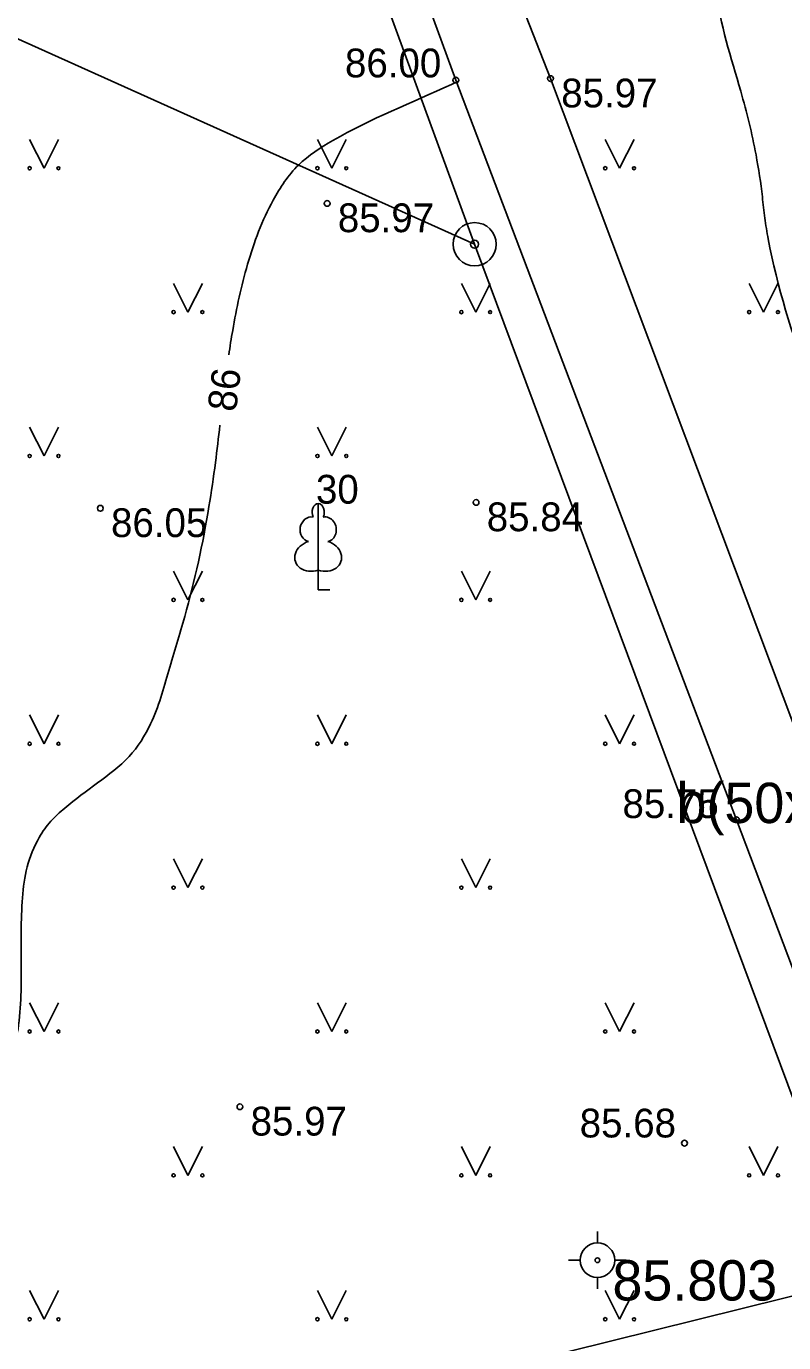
# Model space of a CAD drawing. Extents: x 576692 to 577659, y 273254 to 273799.
# Drawn here: x 576757.19 to 576770.35, y 273657.09 to 273679.97 of the extents above; entities that cross this region are included whole.
import ezdxf

# ---------------------------------------------------------------- set-up
doc = ezdxf.new("R2010")
doc.units = 0
for name, color, linetype in [('APGR_SARK_####_####_#', 7, 'Continuous'), ('BUVE_EKAS_RAKS_TKST_#', 7, 'Continuous'), ('CELI_CAPM_####_####_#', 7, 'Continuous'), ('CELI_CMAL_####_####_#', 7, 'Continuous'), ('CELI_TAKA_####_####_#', 7, 'Continuous'), ('CKOM_DEGV_ELEM_TKST_#', 7, 'Continuous'), ('CKOM_ELEM_####_####_#', 7, 'Continuous'), ('GEOD_ELEM_####_TKST_#', 7, 'Continuous'), ('GEOD_SITP_####_TKST_#', 7, 'Continuous'), ('HIDT_REZV_####_TKST_#', 7, 'Continuous'), ('LKAN_ELEM_PAST_TKST_#', 7, 'Continuous'), ('RELJ_ELEM_####_####_#', 7, 'Continuous'), ('RELJ_HORZ_PAMT_####_#', 7, 'Continuous'), ('SILT_VADP_UDEN_####_#', 7, 'Continuous')]:
    doc.layers.add(name, color=color, linetype=linetype)

msp = doc.modelspace()

# ---------------------------------------------------------------- linework, layer by layer
at = {"layer": 'BUVE_EKAS_RAKS_TKST_#'}
for radius in [0.375, 0.0702]:
    msp.add_circle((576764.98, 273676.18), radius, dxfattribs=at)
at = {"layer": 'CELI_CAPM_####_####_#'}
for points in [[(576773.869, 273658.741), (576773.854, 273658.784), (576773.503, 273659.803), (576770.984, 273666.605), (576766.299, 273679.057), (576764.543, 273683.538), (576764.259, 273684.554), (576764.25, 273685.513), (576764.288, 273686.523), (576764.428, 273692.633), (576764.527, 273693.163), (576767.396, 273701.827), (576768.01, 273703.188), (576772.621, 273713.302), (576777.579, 273724.305)], [(576775.322, 273724.131), (576774.601, 273722.477), (576775.024, 273722.324), (576771.324, 273714.127), (576766.646, 273703.83), (576766.03, 273702.46), (576765.472, 273700.84), (576763.518, 273694.624), (576763.117, 273693.591), (576762.914, 273692.62), (576762.805, 273686.629), (576762.771, 273685.624), (576762.737, 273684.906), (576763.015, 273683.516), (576764.654, 273679.032), (576769.528, 273666.179), (576772.041, 273659.532), (576772.286, 273658.824), (576772.437, 273658.386)]]:
    msp.add_lwpolyline(points, dxfattribs=at)
at = {"layer": 'CELI_TAKA_####_####_#'}
msp.add_lwpolyline([(576848.447, 273595.284), (576850.413, 273611.975), (576839.74, 273611.3), (576799.298, 273680.086), (576786.491, 273690.257), (576780.2, 273683.233), (576786.155, 273661.79), (576765.1, 273656.565), (576764.662, 273653.384), (576732.149, 273649.138), (576726.076, 273650.997), (576719.157, 273649.712), (576724.595, 273660.398), (576733.342, 273685.822), (576746.079, 273731.492)], dxfattribs=at)
at = {"layer": 'CKOM_ELEM_####_####_#'}
for p, q in [((576767.114, 273658.826), (576767.114, 273659.026)), ((576766.614, 273658.526), (576766.814, 273658.526)), ((576767.414, 273658.526), (576767.614, 273658.526)), ((576767.114, 273658.026), (576767.114, 273658.226))]:
    msp.add_line(p, q, dxfattribs=at)
for radius in [0.3, 0.04]:
    msp.add_circle((576767.114, 273658.526), radius, dxfattribs=at)
at = {"layer": 'GEOD_ELEM_####_TKST_#'}
for points in [[(576764.625, 273678.98), (576764.576, 273678.957), (576762.517, 273677.983), (576761.92, 273677.555), (576761.679, 273677.268), (576761.479, 273676.944), (576761.036, 273675.831), (576760.777, 273674.683), (576760.709, 273674.255)], [(576760.556, 273673.037), (576760.477, 273672.385), (576760.365, 273671.62), (576759.945, 273669.712), (576759.669, 273668.774), (576759.351, 273667.846), (576758.977, 273667.278), (576758.429, 273666.82), (576757.86, 273666.381), (576757.617, 273666.152), (576757.511, 273666.02), (576757.418, 273665.873), (576757.206, 273665.36), (576757.125, 273664.825), (576757.103, 273663.643), (576757.036, 273662.469), (576756.887, 273661.93), (576756.608, 273661.447), (576755.986, 273660.73), (576755.306, 273660.08), (576754.566, 273659.505), (576753.765, 273659.015), (576752.999, 273658.642), (576752.222, 273658.3), (576751.454, 273657.95), (576750.71, 273657.551), (576747.619, 273655.722), (576746.907, 273655.289), (576746.201, 273654.848), (576745.493, 273654.408), (576745.12, 273654.182)]]:
    msp.add_spline(points, degree=3, dxfattribs=at)
at = {"layer": 'GEOD_SITP_####_TKST_#'}
msp.add_spline([(576771.012, 273694.903), (576770.897, 273694.749), (576770.848, 273694.681), (576770.769, 273694.511), (576770.586, 273693.743), (576769.497, 273689.762), (576769.267, 273688.405), (576769.27, 273687.222), (576769.378, 273686.039), (576769.501, 273684.856), (576769.548, 273683.673), (576769.52, 273683.23), (576769.451, 273682.81), (576769.357, 273682.394), (576769.262, 273681.979), (576769.188, 273681.562), (576769.176, 273680.6), (576769.604, 273678.839), (576769.869, 273677.731), (576769.979, 273677.003), (576770.021, 273676.635), (576770.081, 273676.271), (576770.793, 273673.833), (576771.261, 273672.65), (576771.782, 273671.484), (576771.987, 273671.135), (576772.039, 273670.993), (576772.601, 273667.751), (576772.598, 273666.644), (576772.546, 273666.09), (576772.472, 273665.54), (576772.28, 273664.711), (576771.998, 273663.9)], degree=3, dxfattribs=at)
at = {"layer": 'LKAN_ELEM_PAST_TKST_#'}
for p, q in [((576757.25, 273678), (576757.5, 273677.5)), ((576757.5, 273677.5), (576757.75, 273678)), ((576762.25, 273678), (576762.5, 273677.5)), ((576762.5, 273677.5), (576762.75, 273678)), ((576767.25, 273678), (576767.5, 273677.5)), ((576767.5, 273677.5), (576767.75, 273678)), ((576759.75, 273675.5), (576760, 273675)), ((576760, 273675), (576760.25, 273675.5)), ((576764.75, 273675.5), (576765, 273675)), ((576765, 273675), (576765.25, 273675.5)), ((576769.75, 273675.5), (576770, 273675)), ((576770, 273675), (576770.25, 273675.5)), ((576757.25, 273673), (576757.5, 273672.5)), ((576757.5, 273672.5), (576757.75, 273673)), ((576762.25, 273673), (576762.5, 273672.5)), ((576762.5, 273672.5), (576762.75, 273673)), ((576759.75, 273670.5), (576760, 273670)), ((576760, 273670), (576760.25, 273670.5)), ((576762.263, 273670.519), (576762.263, 273670.172)), ((576764.75, 273670.5), (576765, 273670)), ((576765, 273670), (576765.25, 273670.5)), ((576762.263, 273670.172), (576762.463, 273670.172)), ((576757.25, 273668), (576757.5, 273667.5)), ((576757.5, 273667.5), (576757.75, 273668)), ((576762.25, 273668), (576762.5, 273667.5)), ((576762.5, 273667.5), (576762.75, 273668)), ((576767.25, 273668), (576767.5, 273667.5)), ((576767.5, 273667.5), (576767.75, 273668)), ((576759.75, 273665.5), (576760, 273665)), ((576760, 273665), (576760.25, 273665.5)), ((576764.75, 273665.5), (576765, 273665)), ((576765, 273665), (576765.25, 273665.5)), ((576757.25, 273663), (576757.5, 273662.5)), ((576757.5, 273662.5), (576757.75, 273663)), ((576762.25, 273663), (576762.5, 273662.5)), ((576762.5, 273662.5), (576762.75, 273663)), ((576767.25, 273663), (576767.5, 273662.5)), ((576767.5, 273662.5), (576767.75, 273663)), ((576759.75, 273660.5), (576760, 273660)), ((576760, 273660), (576760.25, 273660.5)), ((576764.75, 273660.5), (576765, 273660)), ((576765, 273660), (576765.25, 273660.5)), ((576769.75, 273660.5), (576770, 273660)), ((576770, 273660), (576770.25, 273660.5)), ((576757.25, 273658), (576757.5, 273657.5)), ((576757.5, 273657.5), (576757.75, 273658)), ((576762.25, 273658), (576762.5, 273657.5)), ((576762.5, 273657.5), (576762.75, 273658)), ((576767.25, 273658), (576767.5, 273657.5)), ((576767.5, 273657.5), (576767.75, 273658))]:
    msp.add_line(p, q, dxfattribs=at)
for points in [[(576762.263, 273671.672), (576762.263, 273670.519)], [(576762.353, 273671.44), (576762.352, 273671.441)]]:
    msp.add_lwpolyline(points, dxfattribs=at)
for centre, radius in [((576757.25, 273677.5), 0.028), ((576757.75, 273677.5), 0.0263), ((576762.25, 273677.5), 0.028), ((576762.75, 273677.5), 0.0263), ((576767.25, 273677.5), 0.028), ((576767.75, 273677.5), 0.0263), ((576759.75, 273675), 0.028), ((576760.25, 273675), 0.0263), ((576764.75, 273675), 0.028), ((576765.25, 273675), 0.0263), ((576769.75, 273675), 0.028), ((576770.25, 273675), 0.0263), ((576757.25, 273672.5), 0.028), ((576757.75, 273672.5), 0.0263), ((576762.25, 273672.5), 0.028), ((576762.75, 273672.5), 0.0263), ((576759.75, 273670), 0.028), ((576760.25, 273670), 0.0263), ((576764.75, 273670), 0.028), ((576765.25, 273670), 0.0263), ((576757.25, 273667.5), 0.028), ((576757.75, 273667.5), 0.0263), ((576762.25, 273667.5), 0.028), ((576762.75, 273667.5), 0.0263), ((576767.25, 273667.5), 0.028), ((576767.75, 273667.5), 0.0263), ((576759.75, 273665), 0.028), ((576760.25, 273665), 0.0263), ((576764.75, 273665), 0.028), ((576765.25, 273665), 0.0263), ((576757.25, 273662.5), 0.028), ((576757.75, 273662.5), 0.0263), ((576762.25, 273662.5), 0.028), ((576762.75, 273662.5), 0.0263), ((576767.25, 273662.5), 0.028), ((576767.75, 273662.5), 0.0263), ((576759.75, 273660), 0.028), ((576760.25, 273660), 0.0263), ((576764.75, 273660), 0.028), ((576765.25, 273660), 0.0263), ((576769.75, 273660), 0.028), ((576770.25, 273660), 0.0263), ((576757.25, 273657.5), 0.028), ((576757.75, 273657.5), 0.0263), ((576762.25, 273657.5), 0.028), ((576762.75, 273657.5), 0.0263), ((576767.25, 273657.5), 0.028), ((576767.75, 273657.5), 0.0263)]:
    msp.add_circle(centre, radius, dxfattribs=at)
for centre, major_axis, ratio, start_param, end_param in [((576762.263, 273671.522), (0, -0.15), 0.707107, 3.14537, 5.287485), ((576762.263, 273671.522), (0, -0.15), 0.707107, 0.995701, 3.137816), ((576762.135, 273671.227), (-0.039, -0.212), 0.861323, 3.141593, 6.283185), ((576762.391, 273671.227), (0.039, -0.212), 0.861323, 0, 3.141593), ((576762.173, 273670.765), (0.307, 0.095), 0.814445, 1.570796, 4.752015), ((576762.353, 273670.765), (-0.307, 0.095), 0.814445, 1.531171, 4.712389)]:
    msp.add_ellipse(centre, major_axis=major_axis, ratio=ratio, start_param=start_param, end_param=end_param, dxfattribs=at)
at = {"layer": 'RELJ_ELEM_####_####_#'}
for centre in [(576764.654, 273679.032), (576766.299, 273679.057), (576762.418, 273676.889), (576758.478, 273671.591), (576765.005, 273671.693), (576769.528, 273666.179), (576760.903, 273661.192), (576768.626, 273660.56)]:
    msp.add_circle(centre, 0.05, dxfattribs=at)
at = {"layer": 'SILT_VADP_UDEN_####_#'}
for points in [[(576776.102, 273646.342), (576764.98, 273676.18), (576762.24, 273683.67), (576762.48, 273692.95), (576765.79, 273703), (576773.75, 273720.17), (576775.79, 273724.09), (576819.3, 273727.418), (576829.949, 273731.794)], [(576722.81, 273698.708), (576735.14, 273689.6), (576764.98, 273676.18), (576776.102, 273646.342)]]:
    msp.add_lwpolyline(points, dxfattribs=at)
msp.add_lwpolyline([(576735.14, 273689.6), (576743.03, 273718.32), (576773.75, 273720.17), (576765.79, 273703), (576762.48, 273692.95), (576762.24, 273683.67), (576764.98, 273676.18)], close=True, dxfattribs=at)

# ---------------------------------------------------------------- texts
at = {"layer": 'APGR_SARK_####_####_#'}
msp.add_text(' 30', height=0.5, dxfattribs=at).set_placement((576762.038, 273671.672))
at = {"layer": 'CELI_CMAL_####_####_#'}
msp.add_text('b(50x50)', height=0.7, dxfattribs=at).set_placement((576768.487, 273666.122))
at = {"layer": 'CKOM_DEGV_ELEM_TKST_#'}
msp.add_text(' 85.803', height=0.7, dxfattribs=at).set_placement((576767.114, 273657.826))
at = {"layer": 'HIDT_REZV_####_TKST_#'}
for s, p in [(' 86.00', (576762.542, 273679.079)), (' 85.97', (576766.299, 273678.557)), (' 85.97', (576762.418, 273676.389)), (' 86.05', (576758.478, 273671.091)), (' 85.84', (576765.005, 273671.193)), (' 85.75', (576767.363, 273666.209)), (' 85.97', (576760.903, 273660.692)), (' 85.68', (576766.62, 273660.659))]:
    msp.add_text(s, height=0.5, dxfattribs=at).set_placement(p)
at = {"layer": 'RELJ_HORZ_PAMT_####_#'}
msp.add_text('86', height=0.5, rotation=83.0771, dxfattribs=at).set_placement((576760.834, 273673.255))

doc.saveas('drawing.dxf')
